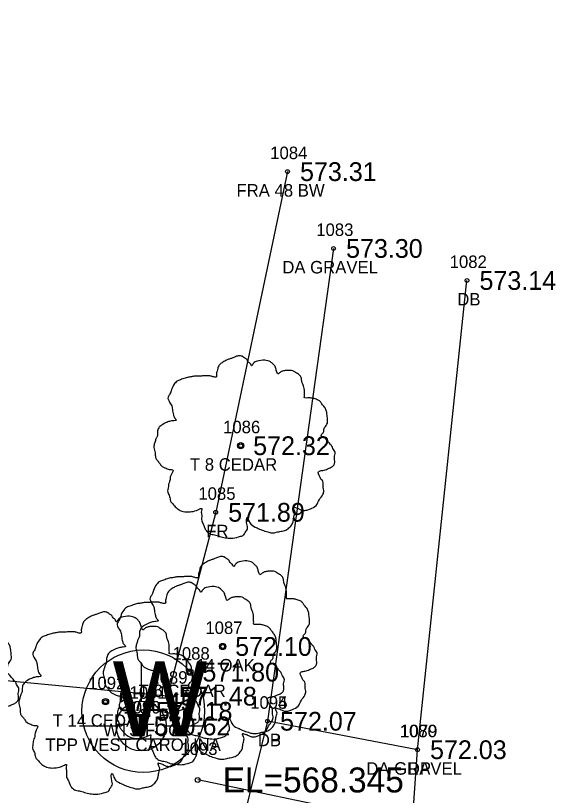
# Model space of a CAD drawing. Extents: x 1529475 to 1532053, y 876698 to 877911.
# Drawn here: x 1531265.9 to 1531309.1, y 877295.3 to 877357.7 of the extents above; entities that cross this region are included whole.
import ezdxf

# ---------------------------------------------------------------- set-up
doc = ezdxf.new("R2010")
doc.units = 0
for name, color, linetype in [('RD_EX_DR_Pipe', 7, 'Continuous'), ('RD_EX_DR_Pipe_txCode', 7, 'Continuous'), ('RD_EX_Driveway', 7, 'Continuous'), ('RD_EX_Driveway_txCode', 7, 'Continuous'), ('RD_EX_Fence_Other', 7, 'Continuous'), ('RD_EX_Fence_Other_txCode', 7, 'Continuous'), ('RD_EX_TX_Driveway_ELEV', 7, 'Continuous'), ('RD_EX_TX_Fence_Other_ELEV', 7, 'Continuous'), ('RD_EX_TX_UT_ELEV', 7, 'Continuous'), ('RD_EX_TX_VEG_ELEV', 7, 'Continuous'), ('RD_EX_UT', 7, 'Continuous'), ('RD_EX_UT_txCode', 7, 'Continuous'), ('RD_EX_VEG', 7, 'Continuous'), ('RD_EX_VEG_txCode', 7, 'Continuous'), ('RD_SMD_Locator', 7, 'Continuous'), ('RD_TX_Pipe_ElevEX', 7, 'Continuous')]:
    doc.layers.add(name, color=color, linetype=linetype)

msp = doc.modelspace()

# ---------------------------------------------------------------- linework, layer by layer
at = {"layer": 'RD_EX_DR_Pipe'}
msp.add_line((1531301.38, 877292.224), (1531280.491, 877296.553), dxfattribs=at)
at = {"layer": 'RD_EX_Driveway'}
for p, q in [((1531291.368, 877339.094), (1531286.084, 877301.254)), ((1531298.088, 877298.975), (1531302.047, 877336.53))]:
    msp.add_line(p, q, dxfattribs=at)
msp.add_lwpolyline([(1531303.666, 877277.444), (1531297.238, 877286.667), (1531298.088, 877298.975), (1531286.084, 877301.254), (1531283.161, 877289.479), (1531276.518, 877282.709)], dxfattribs=at)
at = {"layer": 'RD_EX_Fence_Other'}
msp.add_lwpolyline([(1531287.683, 877345.243), (1531281.932, 877317.977), (1531278.086, 877303.259), (1531232.889, 877307.565), (1531185.71, 877311.458), (1531137.538, 877312.532), (1531141.511, 877357.73)], dxfattribs=at)
at = {"layer": 'RD_EX_UT'}
for p, q in [((1531275.972, 877305.944), (1531275.972, 877302.874)), ((1531271.042, 877300.889), (1531273.972, 877300.889)), ((1531277.972, 877300.889), (1531281.042, 877300.889)), ((1531274.011, 877299.846), (1531278.64, 877299.846))]:
    msp.add_line(p, q, dxfattribs=at)
for centre, radius in [((1531276.139, 877302.054), 4.908), ((1531275.972, 877300.874), 2)]:
    msp.add_circle(centre, radius, dxfattribs=at)
at = {"layer": 'RD_EX_VEG'}
for centre, radius in [((1531283.934, 877323.305), 0.25), ((1531283.921, 877323.286), 0.0001), ((1531282.493, 877307.238), 0.25), ((1531282.481, 877307.219), 0.0001), ((1531279.868, 877305.184), 0.25), ((1531279.855, 877305.165), 0.0001), ((1531273.114, 877302.815), 0.25), ((1531273.101, 877302.796), 0.0001)]:
    msp.add_circle(centre, radius, dxfattribs=at)
for points in [[(1531284.066, 877330.472), (1531283.766, 877330.497), (1531283.441, 877330.397), (1531283.191, 877330.297), (1531282.966, 877330.222), (1531282.741, 877330.122), (1531282.441, 877329.948), (1531282.216, 877329.748), (1531282.091, 877329.498), (1531282.041, 877329.273), (1531281.992, 877328.998), (1531281.992, 877328.823), (1531281.867, 877328.798), (1531281.717, 877328.823), (1531281.467, 877328.898), (1531281.217, 877328.898), (1531280.967, 877328.898), (1531280.617, 877328.873), (1531280.267, 877328.873), (1531279.992, 877328.823), (1531279.668, 877328.773), (1531279.293, 877328.648), (1531278.943, 877328.523), (1531278.643, 877328.273), (1531278.393, 877327.798), (1531278.268, 877327.449), (1531278.118, 877327.199), (1531278.268, 877326.749), (1531278.443, 877326.399), (1531278.468, 877326.199), (1531278.543, 877325.774), (1531278.643, 877325.549), (1531278.768, 877325.349), (1531278.693, 877325.325), (1531278.318, 877325.275), (1531278.018, 877325.175), (1531277.593, 877324.95), (1531277.369, 877324.725), (1531277.269, 877324.4), (1531277.244, 877324.05), (1531277.144, 877323.85), (1531277.069, 877323.575), (1531277.044, 877323.5), (1531276.994, 877323.175), (1531277.094, 877322.726), (1531277.119, 877322.376), (1531277.244, 877322.151), (1531277.394, 877321.976), (1531277.568, 877321.726), (1531277.968, 877321.501), (1531278.293, 877321.401), (1531278.493, 877321.376), (1531278.318, 877320.876), (1531278.268, 877320.527), (1531278.143, 877320.127), (1531278.143, 877320.052), (1531278.093, 877319.577), (1531278.243, 877319.252), (1531278.318, 877318.877), (1531278.493, 877318.652), (1531278.768, 877318.353), (1531279.093, 877318.128), (1531279.593, 877318.003), (1531279.992, 877318.028), (1531280.567, 877318.203), (1531280.817, 877318.278), (1531280.792, 877318.103), (1531280.817, 877317.728), (1531280.817, 877317.303), (1531280.967, 877316.978), (1531281.067, 877316.703), (1531281.217, 877316.453), (1531281.542, 877316.229), (1531281.942, 877316.154), (1531282.366, 877316.004), (1531282.816, 877315.929), (1531283.316, 877315.904), (1531283.916, 877316.054), (1531284.191, 877316.179), (1531284.291, 877316.353), (1531284.49, 877316.728), (1531284.44, 877316.953), (1531284.465, 877317.553), (1531284.565, 877317.378), (1531284.74, 877317.028), (1531285.24, 877316.728), (1531285.64, 877316.553), (1531286.115, 877316.403), (1531286.415, 877316.328), (1531286.889, 877316.403), (1531287.264, 877316.478), (1531287.639, 877316.603), (1531287.939, 877316.878), (1531288.114, 877317.153), (1531288.164, 877317.428), (1531288.239, 877317.803), (1531288.289, 877317.978)], [(1531288.289, 877317.978), (1531288.214, 877318.153), (1531288.164, 877318.403), (1531288.239, 877318.378), (1531288.414, 877318.328), (1531288.689, 877318.203), (1531288.914, 877318.128), (1531289.238, 877318.153), (1531289.513, 877318.253), (1531289.963, 877318.528), (1531290.238, 877319.002), (1531290.513, 877319.402), (1531290.588, 877319.727), (1531290.538, 877319.952), (1531290.513, 877320.452), (1531290.313, 877320.702), (1531290.263, 877320.826), (1531290.163, 877321.226), (1531290.238, 877321.276), (1531290.513, 877321.326), (1531290.888, 877321.451), (1531291.163, 877321.576), (1531291.387, 877321.751), (1531291.462, 877321.976), (1531291.437, 877322.376), (1531291.487, 877322.776), (1531291.412, 877322.926), (1531291.312, 877323.075), (1531291.237, 877323.275), (1531291.088, 877323.425), (1531290.988, 877323.575), (1531290.888, 877323.675), (1531290.763, 877323.825), (1531290.588, 877323.95), (1531290.438, 877324), (1531290.388, 877324.15), (1531290.538, 877324.35), (1531290.588, 877324.45), (1531290.613, 877324.675), (1531290.838, 877325.025), (1531290.888, 877325.424), (1531290.838, 877325.849), (1531290.788, 877326.124), (1531290.638, 877326.399), (1531290.438, 877326.649), (1531290.313, 877326.824), (1531290.138, 877326.949), (1531289.813, 877327.074), (1531289.563, 877327.124), (1531289.213, 877327.124), (1531289.013, 877327.174), (1531289.038, 877327.224), (1531289.038, 877327.374), (1531289.038, 877327.649), (1531288.963, 877328.098), (1531288.814, 877328.598), (1531288.814, 877328.623), (1531288.714, 877328.873), (1531288.489, 877329.073), (1531288.314, 877329.173), (1531288.114, 877329.298), (1531287.864, 877329.323), (1531287.564, 877329.323), (1531287.289, 877329.273), (1531287.089, 877329.173), (1531286.914, 877329.048), (1531286.839, 877329.198), (1531286.739, 877329.498), (1531286.689, 877329.648), (1531286.54, 877329.823), (1531286.315, 877330.022), (1531285.865, 877330.147), (1531285.24, 877330.072), (1531284.94, 877329.873), (1531284.79, 877329.698), (1531284.74, 877329.823), (1531284.54, 877330.022), (1531284.44, 877330.197), (1531284.266, 877330.322), (1531284.116, 877330.422), (1531284.016, 877330.472)], [(1531282.625, 877314.405), (1531282.325, 877314.43), (1531282, 877314.33), (1531281.751, 877314.23), (1531281.526, 877314.155), (1531281.301, 877314.055), (1531281.001, 877313.88), (1531280.776, 877313.68), (1531280.651, 877313.431), (1531280.601, 877313.206), (1531280.551, 877312.931), (1531280.551, 877312.756), (1531280.426, 877312.731), (1531280.276, 877312.756), (1531280.026, 877312.831), (1531279.776, 877312.831), (1531279.526, 877312.831), (1531279.177, 877312.806), (1531278.827, 877312.806), (1531278.552, 877312.756), (1531278.227, 877312.706), (1531277.852, 877312.581), (1531277.502, 877312.456), (1531277.203, 877312.206), (1531276.953, 877311.731), (1531276.828, 877311.381), (1531276.678, 877311.132), (1531276.828, 877310.682), (1531277.003, 877310.332), (1531277.028, 877310.132), (1531277.103, 877309.707), (1531277.203, 877309.482), (1531277.327, 877309.282), (1531277.253, 877309.257), (1531276.878, 877309.207), (1531276.578, 877309.107), (1531276.153, 877308.883), (1531275.928, 877308.658), (1531275.828, 877308.333), (1531275.803, 877307.983), (1531275.703, 877307.783), (1531275.628, 877307.508), (1531275.603, 877307.433), (1531275.553, 877307.108), (1531275.653, 877306.658), (1531275.678, 877306.309), (1531275.803, 877306.084), (1531275.953, 877305.909), (1531276.128, 877305.659), (1531276.528, 877305.434), (1531276.853, 877305.334), (1531277.053, 877305.309), (1531276.878, 877304.809), (1531276.828, 877304.459), (1531276.703, 877304.06), (1531276.703, 877303.985), (1531276.653, 877303.51), (1531276.803, 877303.185), (1531276.878, 877302.81), (1531277.053, 877302.585), (1531277.327, 877302.285), (1531277.652, 877302.061), (1531278.152, 877301.936), (1531278.552, 877301.961), (1531279.127, 877302.135), (1531279.377, 877302.21), (1531279.352, 877302.036), (1531279.377, 877301.661), (1531279.377, 877301.236), (1531279.526, 877300.911), (1531279.626, 877300.636), (1531279.776, 877300.386), (1531280.101, 877300.161), (1531280.501, 877300.086), (1531280.926, 877299.936), (1531281.376, 877299.861), (1531281.875, 877299.836), (1531282.475, 877299.986), (1531282.75, 877300.111), (1531282.85, 877300.286), (1531283.05, 877300.661), (1531283, 877300.886), (1531283.025, 877301.486), (1531283.125, 877301.311), (1531283.3, 877300.961), (1531283.8, 877300.661), (1531284.199, 877300.486), (1531284.674, 877300.336), (1531284.974, 877300.261), (1531285.449, 877300.336), (1531285.824, 877300.411), (1531286.199, 877300.536), (1531286.498, 877300.811), (1531286.673, 877301.086), (1531286.723, 877301.361), (1531286.798, 877301.736), (1531286.848, 877301.911)], [(1531286.848, 877301.911), (1531286.773, 877302.086), (1531286.723, 877302.335), (1531286.798, 877302.31), (1531286.973, 877302.26), (1531287.248, 877302.135), (1531287.473, 877302.061), (1531287.798, 877302.086), (1531288.073, 877302.185), (1531288.523, 877302.46), (1531288.797, 877302.935), (1531289.072, 877303.335), (1531289.147, 877303.66), (1531289.097, 877303.885), (1531289.072, 877304.384), (1531288.872, 877304.634), (1531288.822, 877304.759), (1531288.722, 877305.159), (1531288.797, 877305.209), (1531289.072, 877305.259), (1531289.447, 877305.384), (1531289.722, 877305.509), (1531289.947, 877305.684), (1531290.022, 877305.909), (1531289.997, 877306.309), (1531290.047, 877306.708), (1531289.972, 877306.858), (1531289.872, 877307.008), (1531289.797, 877307.208), (1531289.647, 877307.358), (1531289.547, 877307.508), (1531289.447, 877307.608), (1531289.322, 877307.758), (1531289.147, 877307.883), (1531288.997, 877307.933), (1531288.947, 877308.083), (1531289.097, 877308.283), (1531289.147, 877308.383), (1531289.172, 877308.608), (1531289.397, 877308.957), (1531289.447, 877309.357), (1531289.397, 877309.782), (1531289.347, 877310.057), (1531289.197, 877310.332), (1531288.997, 877310.582), (1531288.872, 877310.757), (1531288.697, 877310.882), (1531288.373, 877311.007), (1531288.123, 877311.057), (1531287.773, 877311.057), (1531287.573, 877311.107), (1531287.598, 877311.157), (1531287.598, 877311.306), (1531287.598, 877311.581), (1531287.523, 877312.031), (1531287.373, 877312.531), (1531287.373, 877312.556), (1531287.273, 877312.806), (1531287.048, 877313.006), (1531286.873, 877313.106), (1531286.673, 877313.231), (1531286.423, 877313.256), (1531286.124, 877313.256), (1531285.849, 877313.206), (1531285.649, 877313.106), (1531285.474, 877312.981), (1531285.399, 877313.131), (1531285.299, 877313.431), (1531285.249, 877313.58), (1531285.099, 877313.755), (1531284.874, 877313.955), (1531284.424, 877314.08), (1531283.8, 877314.005), (1531283.5, 877313.805), (1531283.35, 877313.63), (1531283.3, 877313.755), (1531283.1, 877313.955), (1531283, 877314.13), (1531282.825, 877314.255), (1531282.675, 877314.355), (1531282.575, 877314.405)], [(1531280, 877312.351), (1531279.7, 877312.376), (1531279.375, 877312.276), (1531279.125, 877312.176), (1531278.9, 877312.101), (1531278.675, 877312.001), (1531278.375, 877311.826), (1531278.15, 877311.626), (1531278.025, 877311.376), (1531277.975, 877311.151), (1531277.926, 877310.877), (1531277.926, 877310.702), (1531277.801, 877310.677), (1531277.651, 877310.702), (1531277.401, 877310.777), (1531277.151, 877310.777), (1531276.901, 877310.777), (1531276.551, 877310.752), (1531276.201, 877310.752), (1531275.926, 877310.702), (1531275.602, 877310.652), (1531275.227, 877310.527), (1531274.877, 877310.402), (1531274.577, 877310.152), (1531274.327, 877309.677), (1531274.202, 877309.327), (1531274.052, 877309.077), (1531274.202, 877308.628), (1531274.377, 877308.278), (1531274.402, 877308.078), (1531274.477, 877307.653), (1531274.577, 877307.428), (1531274.702, 877307.228), (1531274.627, 877307.203), (1531274.252, 877307.153), (1531273.952, 877307.053), (1531273.527, 877306.828), (1531273.303, 877306.603), (1531273.203, 877306.279), (1531273.178, 877305.929), (1531273.078, 877305.729), (1531273.003, 877305.454), (1531272.978, 877305.379), (1531272.928, 877305.054), (1531273.028, 877304.604), (1531273.053, 877304.254), (1531273.178, 877304.03), (1531273.328, 877303.855), (1531273.502, 877303.605), (1531273.902, 877303.38), (1531274.227, 877303.28), (1531274.427, 877303.255), (1531274.252, 877302.755), (1531274.202, 877302.405), (1531274.077, 877302.005), (1531274.077, 877301.931), (1531274.027, 877301.456), (1531274.177, 877301.131), (1531274.252, 877300.756), (1531274.427, 877300.531), (1531274.702, 877300.231), (1531275.027, 877300.006), (1531275.527, 877299.881), (1531275.926, 877299.906), (1531276.501, 877300.081), (1531276.751, 877300.156), (1531276.726, 877299.981), (1531276.751, 877299.606), (1531276.751, 877299.182), (1531276.901, 877298.857), (1531277.001, 877298.582), (1531277.151, 877298.332), (1531277.476, 877298.107), (1531277.876, 877298.032), (1531278.3, 877297.882), (1531278.75, 877297.807), (1531279.25, 877297.782), (1531279.85, 877297.932), (1531280.125, 877298.057), (1531280.225, 877298.232), (1531280.424, 877298.607), (1531280.374, 877298.832), (1531280.399, 877299.432), (1531280.499, 877299.257), (1531280.674, 877298.907), (1531281.174, 877298.607), (1531281.574, 877298.432), (1531282.049, 877298.282), (1531282.349, 877298.207), (1531282.823, 877298.282), (1531283.198, 877298.357), (1531283.573, 877298.482), (1531283.873, 877298.757), (1531284.048, 877299.032), (1531284.098, 877299.307), (1531284.173, 877299.681), (1531284.223, 877299.856)], [(1531284.223, 877299.856), (1531284.148, 877300.031), (1531284.098, 877300.281), (1531284.173, 877300.256), (1531284.348, 877300.206), (1531284.623, 877300.081), (1531284.848, 877300.006), (1531285.172, 877300.031), (1531285.447, 877300.131), (1531285.897, 877300.406), (1531286.172, 877300.881), (1531286.447, 877301.281), (1531286.522, 877301.606), (1531286.472, 877301.831), (1531286.447, 877302.33), (1531286.247, 877302.58), (1531286.197, 877302.705), (1531286.097, 877303.105), (1531286.172, 877303.155), (1531286.447, 877303.205), (1531286.822, 877303.33), (1531287.097, 877303.455), (1531287.321, 877303.63), (1531287.396, 877303.855), (1531287.371, 877304.254), (1531287.421, 877304.654), (1531287.346, 877304.804), (1531287.246, 877304.954), (1531287.171, 877305.154), (1531287.022, 877305.304), (1531286.922, 877305.454), (1531286.822, 877305.554), (1531286.697, 877305.704), (1531286.522, 877305.829), (1531286.372, 877305.879), (1531286.322, 877306.029), (1531286.472, 877306.229), (1531286.522, 877306.329), (1531286.547, 877306.553), (1531286.772, 877306.903), (1531286.822, 877307.303), (1531286.772, 877307.728), (1531286.722, 877308.003), (1531286.572, 877308.278), (1531286.372, 877308.528), (1531286.247, 877308.703), (1531286.072, 877308.827), (1531285.747, 877308.952), (1531285.497, 877309.002), (1531285.147, 877309.002), (1531284.947, 877309.052), (1531284.972, 877309.102), (1531284.972, 877309.252), (1531284.972, 877309.527), (1531284.897, 877309.977), (1531284.748, 877310.477), (1531284.748, 877310.502), (1531284.648, 877310.752), (1531284.423, 877310.952), (1531284.248, 877311.051), (1531284.048, 877311.176), (1531283.798, 877311.201), (1531283.498, 877311.201), (1531283.223, 877311.151), (1531283.023, 877311.051), (1531282.848, 877310.927), (1531282.773, 877311.076), (1531282.673, 877311.376), (1531282.623, 877311.526), (1531282.474, 877311.701), (1531282.249, 877311.901), (1531281.799, 877312.026), (1531281.174, 877311.951), (1531280.874, 877311.751), (1531280.724, 877311.576), (1531280.674, 877311.701), (1531280.474, 877311.901), (1531280.374, 877312.076), (1531280.2, 877312.201), (1531280.05, 877312.301), (1531279.95, 877312.351)], [(1531262.976, 877299.088), (1531262.901, 877299.263), (1531262.851, 877299.513), (1531262.926, 877299.488), (1531263.101, 877299.438), (1531263.376, 877299.313), (1531263.601, 877299.238), (1531263.926, 877299.263), (1531264.201, 877299.363), (1531264.65, 877299.638), (1531264.925, 877300.113), (1531265.2, 877300.512), (1531265.275, 877300.837), (1531265.225, 877301.062), (1531265.2, 877301.562), (1531265, 877301.812), (1531264.95, 877301.937), (1531264.85, 877302.337), (1531264.925, 877302.387), (1531265.2, 877302.437), (1531265.575, 877302.562), (1531265.85, 877302.686), (1531266.075, 877302.861), (1531266.15, 877303.086), (1531266.125, 877303.486), (1531266.175, 877303.886), (1531266.1, 877304.036), (1531266, 877304.186), (1531265.925, 877304.386), (1531265.775, 877304.536), (1531265.675, 877304.686), (1531265.575, 877304.786), (1531265.45, 877304.936), (1531265.275, 877305.06), (1531265.125, 877305.11), (1531265.075, 877305.26), (1531265.225, 877305.46), (1531265.275, 877305.56), (1531265.3, 877305.785), (1531265.525, 877306.135), (1531265.575, 877306.535), (1531265.525, 877306.96), (1531265.475, 877307.235), (1531265.325, 877307.509), (1531265.125, 877307.759), (1531265, 877307.934), (1531264.825, 877308.059), (1531264.5, 877308.184), (1531264.251, 877308.234), (1531263.901, 877308.234), (1531263.701, 877308.284), (1531263.726, 877308.334), (1531263.726, 877308.484), (1531263.726, 877308.759), (1531263.651, 877309.209), (1531263.501, 877309.708), (1531263.501, 877309.733), (1531263.401, 877309.983), (1531263.176, 877310.183), (1531263.001, 877310.283), (1531262.801, 877310.408), (1531262.551, 877310.433), (1531262.251, 877310.433), (1531261.977, 877310.383), (1531261.777, 877310.283), (1531261.602, 877310.158), (1531261.527, 877310.308), (1531261.427, 877310.608), (1531261.377, 877310.758), (1531261.227, 877310.933), (1531261.002, 877311.133), (1531260.552, 877311.258), (1531259.927, 877311.183), (1531259.628, 877310.983), (1531259.478, 877310.808), (1531259.428, 877310.933), (1531259.228, 877311.133), (1531259.128, 877311.308), (1531258.953, 877311.433), (1531258.803, 877311.533), (1531258.703, 877311.583)], [(1531273.246, 877309.982), (1531272.946, 877310.007), (1531272.621, 877309.907), (1531272.371, 877309.808), (1531272.146, 877309.733), (1531271.921, 877309.633), (1531271.621, 877309.458), (1531271.396, 877309.258), (1531271.271, 877309.008), (1531271.221, 877308.783), (1531271.172, 877308.508), (1531271.172, 877308.333), (1531271.047, 877308.308), (1531270.897, 877308.333), (1531270.647, 877308.408), (1531270.397, 877308.408), (1531270.147, 877308.408), (1531269.797, 877308.383), (1531269.447, 877308.383), (1531269.172, 877308.333), (1531268.848, 877308.283), (1531268.473, 877308.158), (1531268.123, 877308.033), (1531267.823, 877307.783), (1531267.573, 877307.309), (1531267.448, 877306.959), (1531267.298, 877306.709), (1531267.448, 877306.259), (1531267.623, 877305.909), (1531267.648, 877305.709), (1531267.723, 877305.285), (1531267.823, 877305.06), (1531267.948, 877304.86), (1531267.873, 877304.835), (1531267.498, 877304.785), (1531267.198, 877304.685), (1531266.773, 877304.46), (1531266.549, 877304.235), (1531266.449, 877303.91), (1531266.424, 877303.56), (1531266.324, 877303.36), (1531266.249, 877303.085), (1531266.224, 877303.01), (1531266.174, 877302.686), (1531266.274, 877302.236), (1531266.299, 877301.886), (1531266.424, 877301.661), (1531266.574, 877301.486), (1531266.748, 877301.236), (1531267.148, 877301.011), (1531267.473, 877300.911), (1531267.673, 877300.886), (1531267.498, 877300.387), (1531267.448, 877300.037), (1531267.323, 877299.637), (1531267.323, 877299.562), (1531267.273, 877299.087), (1531267.423, 877298.762), (1531267.498, 877298.388), (1531267.673, 877298.163), (1531267.948, 877297.863), (1531268.273, 877297.638), (1531268.773, 877297.513), (1531269.172, 877297.538), (1531269.747, 877297.713), (1531269.997, 877297.788), (1531269.972, 877297.613), (1531269.997, 877297.238), (1531269.997, 877296.813), (1531270.147, 877296.488), (1531270.247, 877296.213), (1531270.397, 877295.964), (1531270.722, 877295.739), (1531271.122, 877295.664), (1531271.546, 877295.514), (1531271.996, 877295.439), (1531272.496, 877295.414), (1531273.096, 877295.564), (1531273.371, 877295.689), (1531273.471, 877295.864), (1531273.67, 877296.238), (1531273.62, 877296.463), (1531273.645, 877297.063), (1531273.745, 877296.888), (1531273.92, 877296.538), (1531274.42, 877296.238), (1531274.82, 877296.064), (1531275.295, 877295.914), (1531275.595, 877295.839), (1531276.069, 877295.914), (1531276.444, 877295.989), (1531276.819, 877296.114), (1531277.119, 877296.388), (1531277.294, 877296.663), (1531277.344, 877296.938), (1531277.419, 877297.313), (1531277.469, 877297.488)], [(1531277.469, 877297.488), (1531277.394, 877297.663), (1531277.344, 877297.913), (1531277.419, 877297.888), (1531277.594, 877297.838), (1531277.869, 877297.713), (1531278.094, 877297.638), (1531278.418, 877297.663), (1531278.693, 877297.763), (1531279.143, 877298.038), (1531279.418, 877298.512), (1531279.693, 877298.912), (1531279.768, 877299.237), (1531279.718, 877299.462), (1531279.693, 877299.962), (1531279.493, 877300.212), (1531279.443, 877300.337), (1531279.343, 877300.736), (1531279.418, 877300.786), (1531279.693, 877300.836), (1531280.068, 877300.961), (1531280.343, 877301.086), (1531280.567, 877301.261), (1531280.642, 877301.486), (1531280.617, 877301.886), (1531280.667, 877302.286), (1531280.592, 877302.436), (1531280.492, 877302.586), (1531280.417, 877302.786), (1531280.268, 877302.935), (1531280.168, 877303.085), (1531280.068, 877303.185), (1531279.943, 877303.335), (1531279.768, 877303.46), (1531279.618, 877303.51), (1531279.568, 877303.66), (1531279.718, 877303.86), (1531279.768, 877303.96), (1531279.793, 877304.185), (1531280.018, 877304.535), (1531280.068, 877304.935), (1531280.018, 877305.359), (1531279.968, 877305.634), (1531279.818, 877305.909), (1531279.618, 877306.159), (1531279.493, 877306.334), (1531279.318, 877306.459), (1531278.993, 877306.584), (1531278.743, 877306.634), (1531278.393, 877306.634), (1531278.193, 877306.684), (1531278.218, 877306.734), (1531278.218, 877306.884), (1531278.218, 877307.159), (1531278.143, 877307.608), (1531277.994, 877308.108), (1531277.994, 877308.133), (1531277.894, 877308.383), (1531277.669, 877308.583), (1531277.494, 877308.683), (1531277.294, 877308.808), (1531277.044, 877308.833), (1531276.744, 877308.833), (1531276.469, 877308.783), (1531276.269, 877308.683), (1531276.094, 877308.558), (1531276.019, 877308.708), (1531275.919, 877309.008), (1531275.869, 877309.158), (1531275.72, 877309.333), (1531275.495, 877309.533), (1531275.045, 877309.658), (1531274.42, 877309.583), (1531274.12, 877309.383), (1531273.97, 877309.208), (1531273.92, 877309.333), (1531273.72, 877309.533), (1531273.62, 877309.708), (1531273.446, 877309.833), (1531273.296, 877309.932), (1531273.196, 877309.982)]]:
    msp.add_spline(points, degree=3, dxfattribs=at)
at = {"layer": 'RD_SMD_Locator'}
for centre, radius in [((1531287.683, 877345.243), 0.15), ((1531291.368, 877339.094), 0.15), ((1531302.047, 877336.53), 0.15), ((1531283.934, 877323.305), 0.15), ((1531281.932, 877317.977), 0.15), ((1531282.493, 877307.238), 0.15), ((1531279.868, 877305.184), 0.15), ((1531278.086, 877303.259), 0.15), ((1531273.114, 877302.815), 0.15), ((1531276.14, 877302.054), 0.15), ((1531286.084, 877301.254), 0.15), ((1531286.084, 877301.254), 0.15), ((1531275.972, 877300.874), 0.15), ((1531298.088, 877298.975), 0.15), ((1531298.088, 877298.975), 0.15), ((1531280.491, 877296.553), 0.2)]:
    msp.add_circle(centre, radius, dxfattribs=at)

# ---------------------------------------------------------------- texts
at = {"layer": 'RD_EX_DR_Pipe_txCode'}
msp.add_text('1093', height=1, dxfattribs=at).set_placement((1531279.105, 877298.553))
at = {"layer": 'RD_EX_Driveway_txCode'}
for s, p in [('1083', (1531289.982, 877340.094)), ('1082', (1531300.661, 877337.53)), ('DA GRAVEL', (1531287.265, 877337.094)), ('DB', (1531301.268, 877334.53)), ('1094', (1531284.698, 877302.254)), ('1095', (1531284.698, 877302.254)), ('1080', (1531296.663, 877299.975)), ('1079', (1531296.702, 877299.975)), ('DB', (1531285.304, 877299.254)), ('DP', (1531285.304, 877299.254)), ('DA GRAVEL', (1531293.986, 877296.975)), ('DP', (1531297.309, 877296.975))]:
    msp.add_text(s, height=1, dxfattribs=at).set_placement(p)
at = {"layer": 'RD_EX_Fence_Other_txCode'}
for s, p in [('1084', (1531286.297, 877346.243)), ('FRA 48 BW', (1531283.596, 877343.243)), ('1085', (1531280.546, 877318.977)), ('FR', (1531281.176, 877315.977)), ('1089', (1531276.7, 877304.259)), ('FR', (1531277.33, 877301.259))]:
    msp.add_text(s, height=1, dxfattribs=at).set_placement(p)
at = {"layer": 'RD_EX_TX_Driveway_ELEV'}
for s, p in [('573.30', (1531292.368, 877338.344)), ('573.14', (1531303.047, 877335.78)), ('572.07', (1531287.084, 877300.504)), ('572.07', (1531287.084, 877300.504)), ('572.03', (1531299.088, 877298.225)), ('572.03', (1531299.088, 877298.225))]:
    msp.add_text(s, height=1.5, dxfattribs=at).set_placement(p)
at = {"layer": 'RD_EX_TX_Fence_Other_ELEV'}
for s, p in [('573.31', (1531288.683, 877344.493)), ('571.89', (1531282.932, 877317.227)), ('571.48', (1531279.086, 877302.509))]:
    msp.add_text(s, height=1.5, dxfattribs=at).set_placement(p)
at = {"layer": 'RD_EX_TX_UT_ELEV'}
for s, p in [('571.18', (1531277.14, 877301.304)), ('570.62', (1531276.972, 877300.124))]:
    msp.add_text(s, height=1.5, dxfattribs=at).set_placement(p)
at = {"layer": 'RD_EX_TX_VEG_ELEV'}
for s, p in [('572.32', (1531284.934, 877322.555)), ('572.10', (1531283.493, 877306.488)), ('571.80', (1531280.868, 877304.434)), ('571.45', (1531274.114, 877302.065))]:
    msp.add_text(s, height=1.5, dxfattribs=at).set_placement(p)
at = {"layer": 'RD_EX_UT'}
for s, height, p in [('W', 6, (1531273.675, 877300.053)), ('T', 2, (1531275.123, 877299.827))]:
    msp.add_text(s, height=height, dxfattribs=at).set_placement(p)
at = {"layer": 'RD_EX_UT_txCode'}
for s, p in [('1091', (1531275.037, 877303.054)), ('1090', (1531274.547, 877301.874)), ('WTS FOC', (1531272.927, 877300.054)), ('TPP WEST CAROLINA', (1531268.303, 877298.874))]:
    msp.add_text(s, height=1, dxfattribs=at).set_placement(p)
at = {"layer": 'RD_EX_VEG_txCode'}
for s, p in [('1086', (1531282.524, 877324.305)), ('T 8 CEDAR', (1531279.871, 877321.305)), ('1087', (1531281.107, 877308.238)), ('1088', (1531278.482, 877306.184)), ('T 14 OAK', (1531279.194, 877305.238)), ('1092', (1531271.728, 877303.815)), ('T 6 CEDAR', (1531275.757, 877303.184)), ('T 14 CEDAR', (1531268.885, 877300.815))]:
    msp.add_text(s, height=1, dxfattribs=at).set_placement(p)
at = {"layer": 'RD_TX_Pipe_ElevEX'}
msp.add_text('EL=568.345', height=2, dxfattribs=at).set_placement((1531282.491, 877295.553))

doc.saveas('drawing.dxf')
